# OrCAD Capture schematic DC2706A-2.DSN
size B
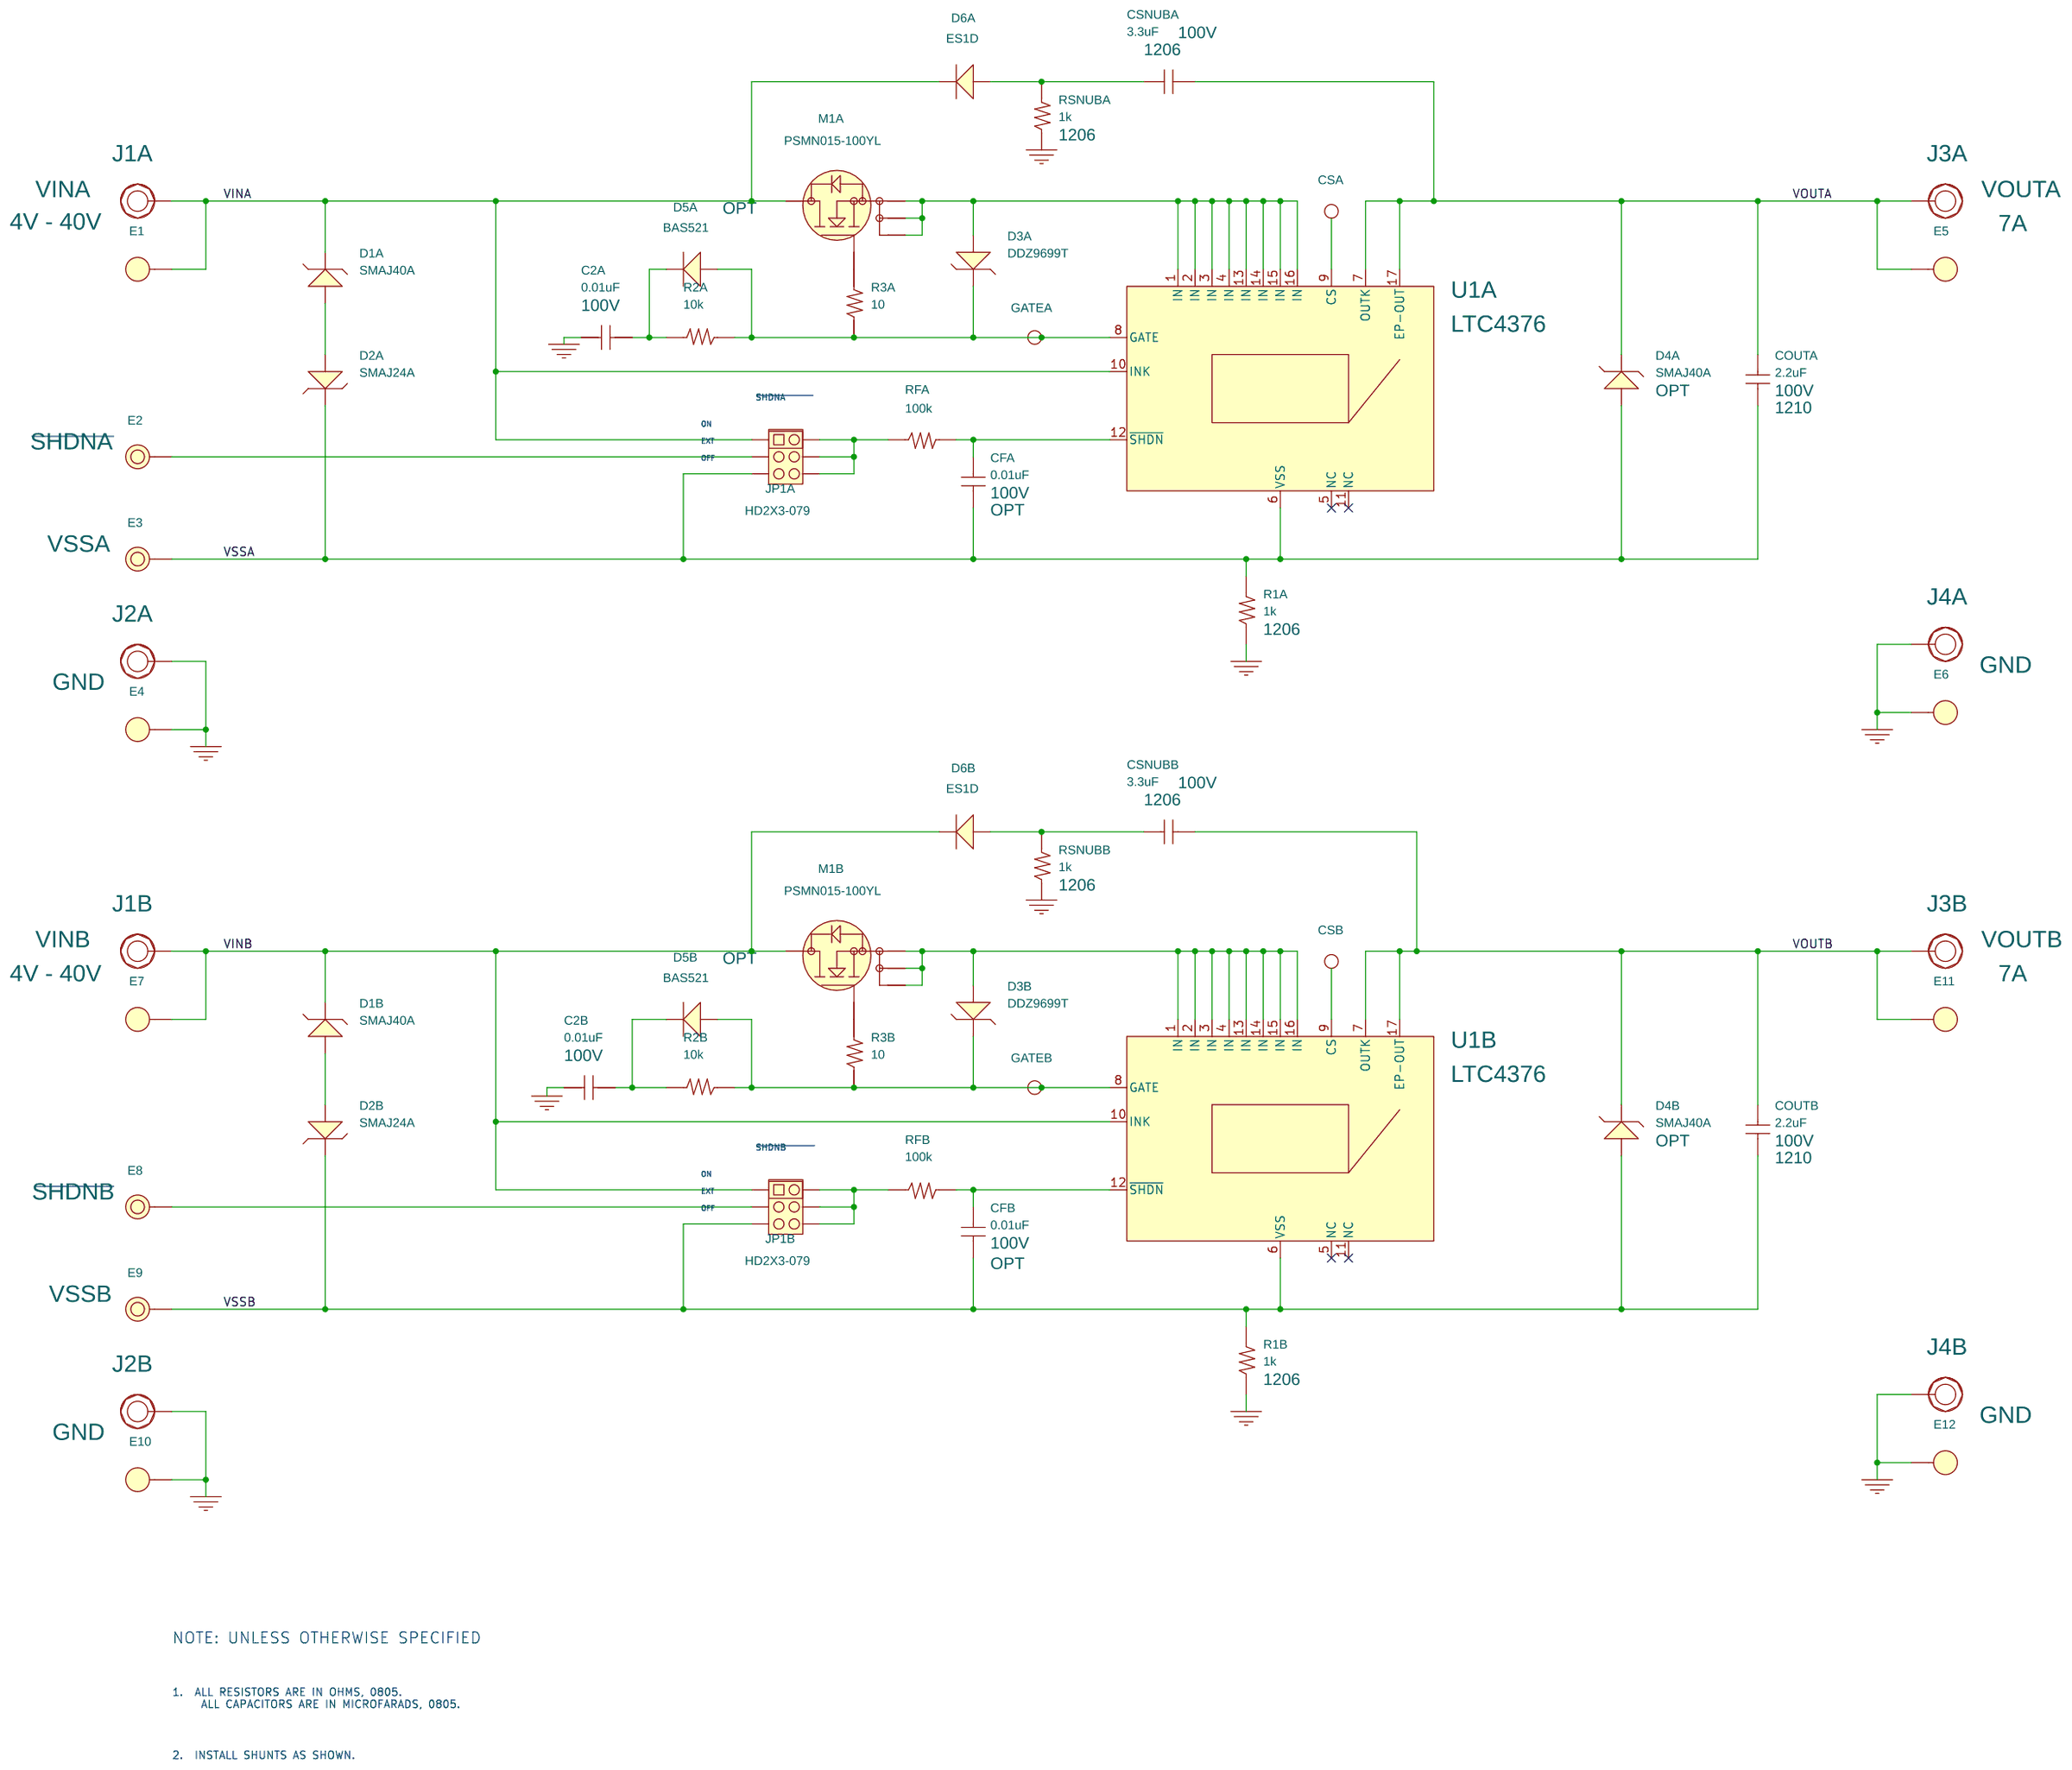
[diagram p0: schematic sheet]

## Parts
C2A  0.01uF  [0805]
C2B  0.01uF  [0805]
CFA  0.01uF  [0805]
CFB  0.01uF  [0805]
COUTA  2.2uF  [1210]
COUTB  2.2uF  [1210]
CSA  PAD100SMT  [PAD100SMT]
CSB  PAD100SMT  [PAD100SMT]
CSNUBA  3.3uF  [1206]
CSNUBB  3.3uF  [1206]
D1A  SMAJ40A  [SMA-DIODE]
D1B  SMAJ40A  [SMA-DIODE]
D2A  SMAJ24A  [SMA-DIODE]
D2B  SMAJ24A  [SMA-DIODE]
D3A  DDZ9699T  [SOD523]
D3B  DDZ9699T  [SOD523]
D4A  SMAJ40A  [SMA-DIODE]
D4B  SMAJ40A  [SMA-DIODE]
D5A  BAS521  [SOD523]
D5B  BAS521  [SOD523]
D6A  ES1D  [SMA-DIODE]
D6B  ES1D  [SMA-DIODE]
E1  MIL-MAX-2501  [MILL-MAX-2501]
E2  MIL-MAX-2308  [MILL-MAX-2308]
E3  MIL-MAX-2308  [MILL-MAX-2308]
E4  MIL-MAX-2501  [MILL-MAX-2501]
E5  MIL-MAX-2501  [MILL-MAX-2501]
E6  MIL-MAX-2501  [MILL-MAX-2501]
E7  MIL-MAX-2501  [MILL-MAX-2501]
E8  MIL-MAX-2308  [MILL-MAX-2308]
E9  MIL-MAX-2308  [MILL-MAX-2308]
E10  MIL-MAX-2501  [MILL-MAX-2501]
E11  MIL-MAX-2501  [MILL-MAX-2501]
E12  MIL-MAX-2501  [MILL-MAX-2501]
GATEA  PAD100SMT  [PAD100SMT]
GATEB  PAD100SMT  [PAD100SMT]
J1A  Banana Jack  [KEY-575]
J1B  Banana Jack  [KEY-575]
J2A  Banana Jack  [KEY-575]
J2B  Banana Jack  [KEY-575]
J3A  Banana Jack  [KEY-575]
J3B  Banana Jack  [KEY-575]
J4A  Banana Jack  [KEY-575]
J4B  Banana Jack  [KEY-575]
JP1A  HD2X3-079  [HD2X3-079]
JP1B  HD2X3-079  [HD2X3-079]
M1A  PSMN015-100YL  [LFPAK56]
M1B  PSMN015-100YL  [LFPAK56]
R1A  1k  [1206]
R1B  1k  [1206]
R2A  10k  [0805]
R2B  10k  [0805]
R3A  10  [0805]
R3B  10  [0805]
RFA  100k  [0805]
RFB  100k  [0805]
RSNUBA  1k  [1206]
RSNUBB  1k  [1206]
U1A  LTC4376  [DFN16DHD-5X4]
U1B  LTC4376  [DFN16DHD-5X4]

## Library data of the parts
C2A C2B COUTA COUTB CSNUBA CSNUBB = CAP-NP: VOLTAGE: 100V
CFA CFB = CAP-NP: OPT: OPT; VOLTAGE: 100V
CSA CSB GATEA GATEB = E-100-25
D1A D1B D2A D2B = SMAJ40A-SMA-DIODE
D3A D3B = DIODE-DDZ9699T-SOD523
D4A D4B = SMAJ40A-SMA-DIODE: OPT: OPT
D5A D5B = DIODE-BAS521-SOD523: OPT: OPT
D6A D6B = DIODE-ES1D-SMA-DIODE
E1 E4-E7 E10-E12 = E-094
E2 = E-064: 1ST PART FIELD: SHDNA
E3 = E-064: 1ST PART FIELD: VSSA
E8 = E-064: 1ST PART FIELD: SHDNB
E9 = E-064: 1ST PART FIELD: VSSB
J1A = E-KEY-575: 1ST PART FIELD: 4V - 40V; FUNTION: VINA
J1B = E-KEY-575: 1ST PART FIELD: 4V - 40V; FUNTION: VINB
J2A J2B J4A J4B = E-KEY-575: FUNTION: GND
J3A = E-KEY-575: 1ST PART FIELD: 7A; FUNTION: VOUTA
J3B = E-KEY-575: 1ST PART FIELD: 7A; FUNTION: VOUTB
JP1A JP1B = HD2X3-079_0
M1A M1B = MOSFET_N-DIODE-PSMN015-LFPAK56
R1A R1B R2A R2B R3A R3B RFA RFB RSNUBA RSNUBB = R
U1A U1B = LTC4376IDHD-DFN16DHD-5X4-DC2706

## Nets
GND: C2A.1 C2B.1 E4.1(A) E6.1(A) E10.1(A) E12.1(A) J2A.1 J2B.1 J4A.1 J4B.1 R1A.1 R1B.1 RSNUBA.1 RSNUBB.1
VINA: D1A.1 D6A.1 E1.1(A) J1A.1 JP1A.1 M1A.5 U1A.10(INK)
VINB: D1B.1 D6B.1 E7.1(A) J1B.1 JP1B.1 M1B.5 U1B.10(INK)
VSSA: CFA.2 COUTA.2 D2A.1 D4A.2 E3.1(A) JP1A.5 R1A.2 U1A.6(VSS)
VSSB: CFB.2 COUTB.2 D2B.1 D4B.2 E9.1(A) JP1B.5 R1B.2 U1B.6(VSS)
VOUTA: COUTA.1 CSNUBA.2 D4A.1 E5.1(A) J3A.1 U1A.7(OUTK) U1A.17(EP-OUT)
VOUTB: COUTB.1 CSNUBB.2 D4B.1 E11.1(A) J3B.1 U1B.7(OUTK) U1B.17(EP-OUT)
N00685: D3A.1 D5A.2 GATEA.1 R2A.1 R3A.1 U1A.8(GATE)
N00699: D3A.2 M1A.1 M1A.2 M1A.3 U1A.1(IN) U1A.2(IN) U1A.3(IN) U1A.4(IN) U1A.13(IN) U1A.14(IN) U1A.15(IN) U1A.16(IN)
N00951: CFA.1 RFA.2 U1A.12(~{SHDN})
N01382: CSA.1 U1A.9(CS)
N02836: CSNUBA.1 D6A.2 RSNUBA.2
N04073: JP1A.2 JP1A.4 JP1A.6 RFA.1
N04138: E2.1(A) JP1A.3
N05364: D1A.2 D2A.2
N09423: D3B.1 D5B.2 GATEB.1 R2B.1 R3B.1 U1B.8(GATE)
N09441: D3B.2 M1B.1 M1B.2 M1B.3 U1B.1(IN) U1B.2(IN) U1B.3(IN) U1B.4(IN) U1B.13(IN) U1B.14(IN) U1B.15(IN) U1B.16(IN)
N09453: CFB.1 RFB.2 U1B.12(~{SHDN})
N09569: CSB.1 U1B.9(CS)
N09887: JP1B.2 JP1B.4 JP1B.6 RFB.1
N09911: E8.1(A) JP1B.3
N10061: D1B.2 D2B.2
N25764: C2A.2 D5A.1 R2A.2
N29094: C2B.2 D5B.1 R2B.2
N34079: CSNUBB.1 D6B.2 RSNUBB.2
N34707: M1B.4 R3B.2
N34709: M1A.4 R3A.2

Not connected (* = marked no-connect by the designer): U1A 5(NC)* 11(NC)*; U1B 5(NC)* 11(NC)*

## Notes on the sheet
- SHDNA
- ON
- EXT
- OFF
- SHDNB
- EXT
- ON
- OFF
- NOTE: UNLESS OTHERWISE SPECIFIED
- 1.  ALL RESISTORS ARE IN OHMS, 0805.
       ALL CAPACITORS ARE IN MICROFARADS, 0805.
- 2.  INSTALL SHUNTS AS SHOWN.
